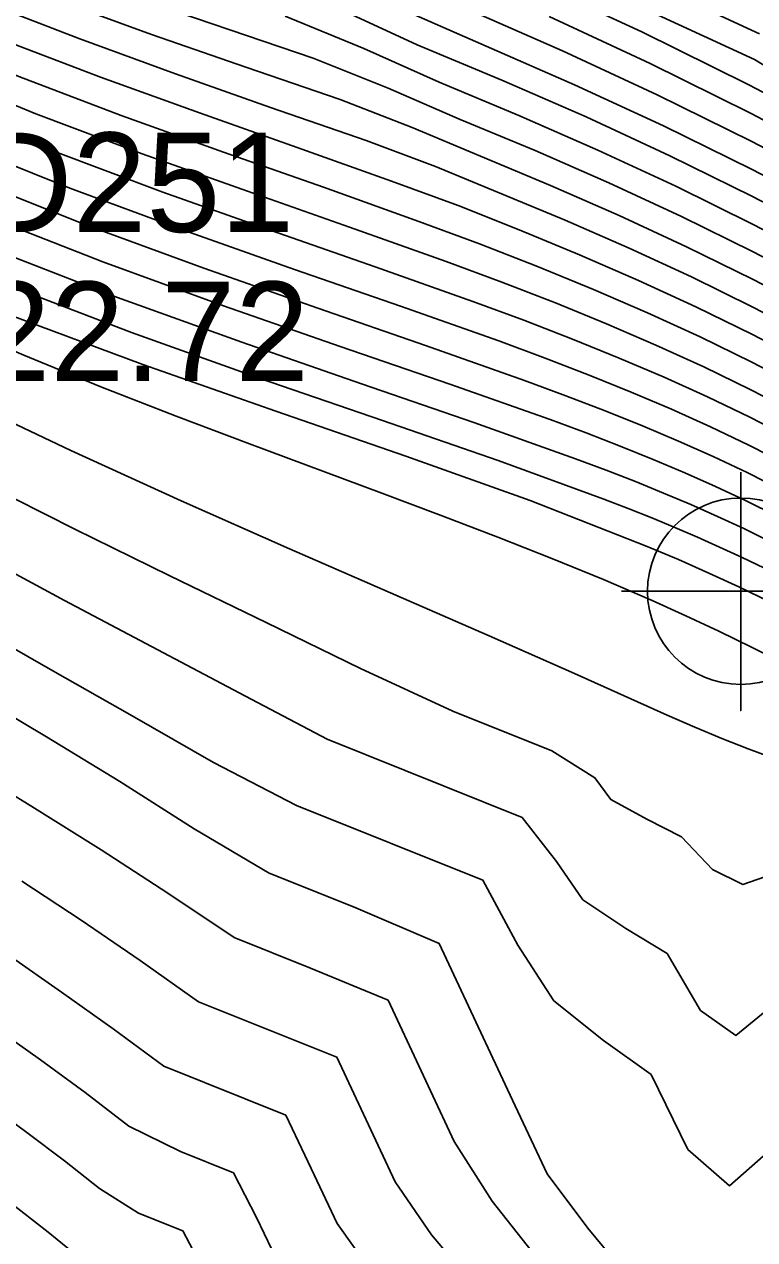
# Model space of a CAD drawing. Extents: x 2356077 to 2359823, y 225951 to 227822.
# Drawn here: x 2356737.94 to 2356756.31, y 227148.02 to 227178.59 of the extents above; entities that cross this region are included whole.
import ezdxf

# ---------------------------------------------------------------- set-up
doc = ezdxf.new("R2010")
doc.units = 0
for name, color, linetype in [('DTM Contours Major', 7, 'Continuous'), ('DTM Contours Minor', 7, 'Continuous'), ('Exist DTM Regular Point CELL', 7, 'Continuous'), ('Exist DTM Regular Point Cogo Elevation', 7, 'Continuous'), ('Exist DTM Regular Point Cogo Number', 7, 'Continuous')]:
    doc.layers.add(name, color=color, linetype=linetype)

msp = doc.modelspace()

# ---------------------------------------------------------------- linework, layer by layer
at = {"layer": 'DTM Contours Major'}
for points in [[(2356740.569, 227179.326), (2356745.206, 227177.74), (2356747.089, 227176.987), (2356748.9, 227176.2), (2356750.782, 227175.418), (2356752.637, 227174.605), (2356754.466, 227173.755), (2356756.272, 227172.865), (2356758.184, 227171.863)], [(2356725.493, 227179.017), (2356728.202, 227177.269), (2356731.02, 227175.731), (2356733.917, 227174.27), (2356737.107, 227172.955), (2356740.279, 227171.721), (2356743.406, 227170.591), (2356746.417, 227169.548), (2356749.239, 227168.577), (2356751.801, 227167.662), (2356752.569, 227167.373), (2356753.306, 227167.086), (2356754.016, 227166.798), (2356754.703, 227166.507), (2356755.373, 227166.21), (2356756.029, 227165.905), (2356756.722, 227165.566)], [(2356751.138, 227178.786), (2356753.675, 227177.603), (2356756.204, 227176.355), (2356758.883, 227174.949)], [(2356733.018, 227178.595), (2356735.579, 227177.425), (2356738.225, 227176.343), (2356740.9, 227175.336), (2356743.548, 227174.39), (2356746.115, 227173.491), (2356748.544, 227172.625), (2356749.95, 227172.103), (2356751.293, 227171.581), (2356752.581, 227171.056), (2356753.824, 227170.521), (2356755.03, 227169.971), (2356756.21, 227169.399), (2356757.454, 227168.758)], [(2356736.915, 227167.049), (2356739.205, 227165.894), (2356741.6, 227164.719), (2356744.023, 227163.543), (2356746.394, 227162.386), (2356748.718, 227161.311), (2356751.203, 227160.315), (2356752.288, 227159.639), (2356752.686, 227159.086), (2356753.596, 227158.591), (2356754.462, 227158.153), (2356755.244, 227157.327), (2356756.006, 227156.951), (2356756.947, 227157.278)], [(2356749.148, 227146.988), (2356748.176, 227148.138), (2356747.267, 227149.469), (2356745.798, 227152.607), (2356742.316, 227154.003), (2356740.852, 227155.04), (2356739.368, 227156.052), (2356737.872, 227157.033)]]:
    msp.add_lwpolyline(points, dxfattribs=at)
at = {"layer": 'DTM Contours Minor'}
for points in [[(2356722.447, 227180.293), (2356728.056, 227176.56), (2356731.037, 227174.934), (2356734.068, 227173.407), (2356737.369, 227172.087), (2356740.632, 227170.839), (2356743.845, 227169.693), (2356746.942, 227168.627), (2356749.853, 227167.62), (2356752.512, 227166.649), (2356753.125, 227166.411), (2356753.72, 227166.173), (2356754.301, 227165.933), (2356754.868, 227165.689), (2356755.425, 227165.441), (2356755.973, 227165.187), (2356756.554, 227164.907)], [(2356721.803, 227179.97), (2356727.804, 227175.976), (2356730.95, 227174.187), (2356734.131, 227172.575), (2356737.541, 227171.293), (2356740.918, 227170.033), (2356744.265, 227168.858), (2356747.53, 227167.729), (2356750.661, 227166.608), (2356753.606, 227165.457), (2356754.388, 227165.126), (2356755.154, 227164.787), (2356755.908, 227164.438), (2356756.706, 227164.052)], [(2356725.879, 227179.529), (2356728.374, 227177.967), (2356731.029, 227176.5), (2356733.794, 227175.123), (2356736.843, 227173.819), (2356739.911, 227172.614), (2356742.949, 227171.507), (2356745.883, 227170.485), (2356748.643, 227169.536), (2356751.159, 227168.646), (2356752.064, 227168.31), (2356752.927, 227167.977), (2356753.754, 227167.645), (2356754.55, 227167.309), (2356755.323, 227166.966), (2356756.077, 227166.612), (2356756.873, 227166.217)], [(2356728.596, 227179.45), (2356730.939, 227178.114), (2356733.416, 227176.868), (2356736.217, 227175.621), (2356739.08, 227174.473), (2356741.942, 227173.412), (2356744.737, 227172.425), (2356747.403, 227171.501), (2356749.874, 227170.625), (2356751.038, 227170.195), (2356752.144, 227169.768), (2356753.2, 227169.341), (2356754.215, 227168.909), (2356755.198, 227168.466), (2356756.156, 227168.007), (2356757.166, 227167.492)], [(2356732.827, 227179.457), (2356735.265, 227178.325), (2356737.798, 227177.278), (2356740.376, 227176.3), (2356742.947, 227175.376), (2356745.459, 227174.492), (2356747.862, 227173.633), (2356749.384, 227173.066), (2356750.843, 227172.497), (2356752.249, 227171.921), (2356753.609, 227171.332), (2356754.934, 227170.725), (2356756.231, 227170.093), (2356757.6, 227169.383)], [(2356750.77, 227179.655), (2356753.466, 227178.398), (2356756.156, 227177.07), (2356759.005, 227175.575)], [(2356754.175, 227179.401), (2356756.428, 227178.349)], [(2356719.033, 227179.275), (2356721.383, 227177.665), (2356723.922, 227176.037), (2356726.585, 227174.423), (2356729.311, 227172.857), (2356732.034, 227171.369), (2356733.322, 227170.693), (2356734.504, 227170.089), (2356735.899, 227169.395), (2356736.368, 227169.166), (2356739.109, 227167.867), (2356741.879, 227166.606), (2356744.605, 227165.399), (2356749.626, 227163.211), (2356751.775, 227162.263), (2356754.102, 227161.212), (2356754.801, 227160.906), (2356755.479, 227160.623), (2356756.145, 227160.362), (2356756.797, 227160.125)], [(2356721.271, 227179.265), (2356723.115, 227178.088), (2356725.109, 227176.86), (2356727.224, 227175.61), (2356729.429, 227174.367), (2356731.694, 227173.16), (2356734.037, 227171.797), (2356735.965, 227171.11), (2356737.927, 227170.264), (2356739.863, 227169.474), (2356741.758, 227168.734), (2356743.6, 227168.037), (2356746.933, 227166.794), (2356748.424, 227166.233), (2356749.848, 227165.686), (2356751.207, 227165.151), (2356752.5, 227164.622), (2356753.729, 227164.094), (2356754.576, 227163.713), (2356755.407, 227163.322), (2356756.242, 227162.915), (2356757.08, 227162.492)], [(2356734.956, 227179.225), (2356737.375, 227178.211), (2356739.854, 227177.263), (2356742.344, 227176.363), (2356744.798, 227175.495), (2356747.17, 227174.644), (2356748.848, 227174.034), (2356750.379, 227173.417), (2356751.902, 227172.79), (2356753.383, 227172.146), (2356754.829, 227171.48), (2356756.247, 227170.786), (2356757.746, 227170.006)], [(2356736.957, 227179.143), (2356739.334, 227178.224), (2356741.74, 227177.348), (2356744.133, 227176.498), (2356746.533, 227175.664), (2356748.277, 227175.012), (2356751.543, 227173.663), (2356753.146, 227172.963), (2356754.716, 227172.237), (2356756.26, 227171.479), (2356757.892, 227170.627)], [(2356738.817, 227179.183), (2356741.137, 227178.332), (2356743.505, 227177.511), (2356745.885, 227176.697), (2356747.69, 227175.996), (2356749.407, 227175.27), (2356751.169, 227174.539), (2356752.897, 227173.783), (2356754.595, 227172.995), (2356756.268, 227172.172), (2356758.038, 227171.246)], [(2356730.895, 227178.918), (2356733.215, 227177.732), (2356735.897, 227176.523), (2356738.653, 227175.407), (2356741.422, 227174.372), (2356744.146, 227173.405), (2356746.763, 227172.493), (2356749.215, 227171.622), (2356750.502, 227171.145), (2356751.726, 227170.672), (2356752.898, 227170.196), (2356754.026, 227169.714), (2356755.118, 227169.218), (2356756.185, 227168.705), (2356757.309, 227168.129)], [(2356744.5, 227178.792), (2356746.473, 227177.985), (2356748.375, 227177.134), (2356750.378, 227176.3), (2356752.362, 227175.429), (2356754.326, 227174.517), (2356756.269, 227173.559), (2356758.327, 227172.48)], [(2356745.836, 227178.992), (2356747.821, 227178.074), (2356749.948, 227177.189), (2356752.065, 227176.26), (2356754.169, 227175.283), (2356756.255, 227174.256), (2356758.465, 227173.098)], [(2356747.332, 227179.011), (2356751.772, 227177.069), (2356754.015, 227176.033), (2356756.243, 227174.941), (2356758.605, 227173.707)], [(2356749.086, 227178.973), (2356751.47, 227177.923), (2356753.857, 227176.814), (2356756.232, 227175.645), (2356758.749, 227174.326)], [(2356753.756, 227178.883), (2356756.304, 227177.703), (2356759.181, 227175.946)], [(2356728.487, 227178.709), (2356730.986, 227177.307), (2356733.613, 227175.997), (2356736.535, 227174.717), (2356739.503, 227173.538), (2356742.453, 227172.453), (2356745.318, 227171.448), (2356748.03, 227170.512), (2356750.521, 227169.632), (2356751.558, 227169.248), (2356752.543, 227168.87), (2356753.484, 227168.491), (2356754.389, 227168.108), (2356755.265, 227167.716), (2356756.119, 227167.312), (2356757.019, 227166.859)], [(2356739.22, 227147.656), (2356738.539, 227148.204), (2356737.848, 227148.744), (2356737.144, 227149.282), (2356733.633, 227151.925), (2356732.661, 227152.665), (2356731.672, 227153.428), (2356730.668, 227154.215), (2356729.366, 227155.256), (2356728.043, 227156.333), (2356725.345, 227158.559), (2356722.591, 227160.834), (2356720.777, 227162.311), (2356718.55, 227164.097), (2356714.836, 227167.056), (2356711.872, 227169.445), (2356708.786, 227171.989), (2356705.713, 227174.611), (2356702.786, 227177.235)], [(2356736.895, 227165.202), (2356738.952, 227164.098), (2356743.345, 227161.775), (2356745.553, 227160.605), (2356750.456, 227158.639), (2356751.321, 227157.526), (2356751.986, 227156.567), (2356753.068, 227155.843), (2356754.102, 227155.217), (2356754.944, 227153.783), (2356755.834, 227153.156), (2356757.121, 227154.206)], [(2356736.763, 227163.409), (2356738.656, 227162.329), (2356740.651, 227161.198), (2356742.692, 227160.021), (2356744.786, 227158.937), (2356749.472, 227157.059), (2356750.348, 227155.425), (2356751.257, 227154.028), (2356752.503, 227153.027), (2356753.704, 227152.169), (2356754.623, 227150.286), (2356755.674, 227149.371), (2356757.225, 227150.734)], [(2356736.723, 227161.72), (2356738.498, 227160.665), (2356740.343, 227159.546), (2356742.206, 227158.351), (2356744.099, 227157.238), (2356746.213, 227156.39), (2356748.373, 227155.471), (2356750.214, 227151.527), (2356751.087, 227149.671), (2356752.111, 227148.305), (2356753.073, 227147.137)], [(2356750.712, 227147.713), (2356749.707, 227148.985), (2356748.745, 227150.489), (2356747.086, 227154.042), (2356745.135, 227154.848), (2356743.219, 227155.616), (2356741.549, 227156.73), (2356739.871, 227157.826), (2356738.196, 227158.871), (2356736.562, 227159.877)], [(2356746.635, 227147.256), (2356745.803, 227148.42), (2356745.156, 227149.807), (2356744.512, 227151.148), (2356741.444, 227152.378), (2356740.172, 227153.318), (2356738.876, 227154.247), (2356737.555, 227155.162)], [(2356744.357, 227147.365), (2356743.776, 227148.576), (2356743.198, 227149.699), (2356741.865, 227150.234), (2356740.567, 227150.876), (2356739.472, 227151.716), (2356738.342, 227152.543), (2356737.182, 227153.365)], [(2356742.42, 227147.297), (2356741.922, 227148.236), (2356740.807, 227148.683), (2356739.833, 227149.306), (2356738.947, 227150.003), (2356738.039, 227150.688), (2356737.111, 227151.37)]]:
    msp.add_lwpolyline(points, dxfattribs=at)
at = {"layer": 'Exist DTM Regular Point CELL'}
msp.add_lwpolyline([(2356755.954, 227167.328), (2356755.954, 227161.328), (2356755.954, 227164.328), (2356758.954, 227164.328), (2356752.954, 227164.328)], dxfattribs=at)
msp.add_circle((2356755.954, 227164.328), 2.344, dxfattribs=at)

# ---------------------------------------------------------------- texts
at = {"layer": 'Exist DTM Regular Point Cogo Elevation'}
msp.add_text('22.72', height=2.5, dxfattribs=at).set_placement((2356736.736, 227169.617))
at = {"layer": 'Exist DTM Regular Point Cogo Number'}
msp.add_text('D251', height=2.5, dxfattribs=at).set_placement((2356736.736, 227173.367))

doc.saveas('drawing.dxf')
